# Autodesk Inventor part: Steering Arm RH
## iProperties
Shininess: 70.0
Angle Display Precision: 2
Document Length Units: 11269
Document Angle Units: 11279
Document Time Units: 11290
Document Mass Units: 11283
Document Length Units Precision: 3
Document Angle Units Precision: 2
Compacted: True
Created: 2001-08
Part Number: Steering Arm RH
Document SubType Name: Modeling
Designer: Martin Budgell
Density: 0.0
Volumn: 0.0
Area: 0.0
PropertySet Name: Model Information
Control State: 0
Master: False
Checked Out: False
Author: Martin Budgell
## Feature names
1. Extrusion1
2. Extrusion2
3. Fillet1
4. Hole1
5. Extrusion3
6. Chamfer1
7. Chamfer2
